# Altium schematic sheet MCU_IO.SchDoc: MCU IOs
size A3; Date: Not used; ApprovedBy: Not used; CheckedBy: Not used; Author: Not used; CompanyName: STMicroelectronics; DrawnBy: Not used; Engineer: Not used; Organization: Not used; Address1: Not used; Address2: Not used; Address3: Not used; Address4: Not used; DocumentNumber: 3; Revision: Not used; SheetNumber: 3; SheetTotal: 16
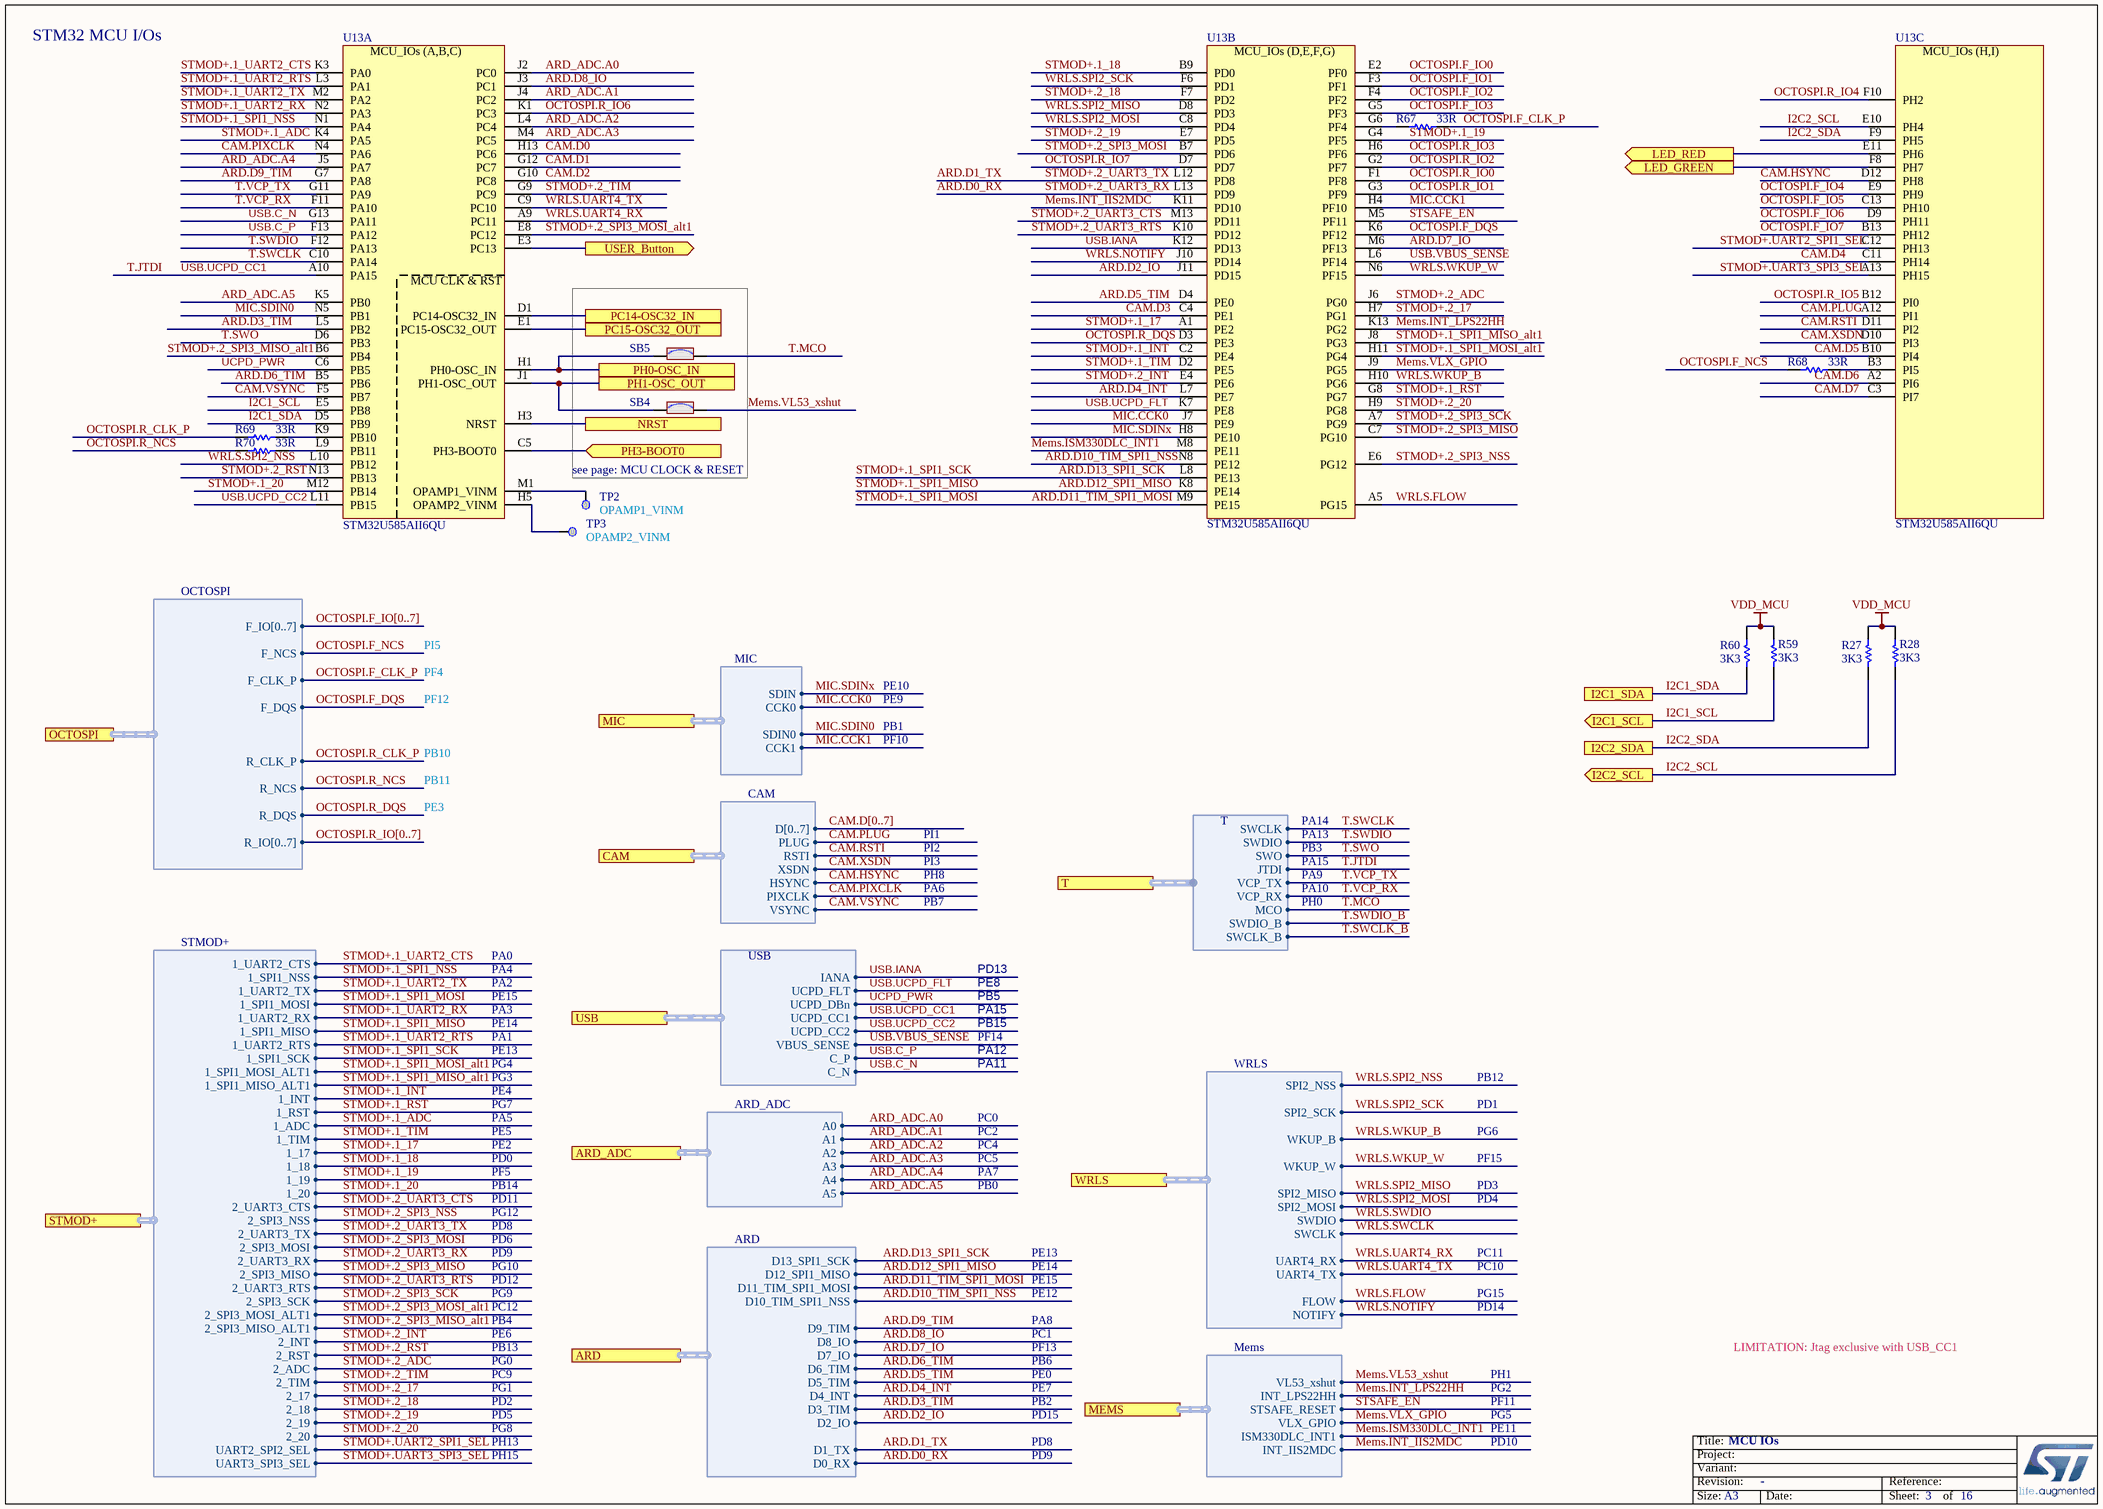
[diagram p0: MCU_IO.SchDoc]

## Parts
R27  value 3K3  [R0603]  (hidden comment: Resistor)
R28  value 3K3  [R0603]  (hidden comment: Resistor)
R59  value 3K3  [R0603]  (hidden comment: Resistor)
R60  value 3K3  [R0603]  (hidden comment: Resistor)
R67  value 33R  [R0402]  (hidden comment: Resistor)
R68  value 33R  [R0402]  (hidden comment: Resistor)
R69  value 33R  [R0402]  (hidden comment: Resistor)
R70  value 33R  [R0402]  (hidden comment: Resistor)
SB4  (no value)  [SOLDER-BRIDGE_R0603-0R]
SB5  (no value)  [SOLDER-BRIDGE_R0603-0R]
TP2  value OPAMP1_VINM  [TP_SMD_1MM]  (no BOM)
TP3  value OPAMP2_VINM  [TP_SMD_1MM]  (no BOM)
U13  STM32U585AII6QU  [ICC_UFBGA169_7X7_P050]  (parts A,B,C of 4)

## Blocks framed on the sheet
see page: MCU CLOCK & RESET: SB4 SB5

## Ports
ARD (harness ARD), ARD_ADC (harness ARD_ADC), CAM (harness CAM), I2C1_SCL (out), I2C1_SDA, I2C2_SCL (out), I2C2_SDA, LED_GREEN (out), LED_RED (out), MEMS (harness Mems), MIC (harness MIC), NRST, OCTOSPI (harness OCTOSPI), PC14-OSC32_IN, PC15-OSC32_OUT, PH0-OSC_IN, PH1-OSC_OUT, PH3-BOOT0 (in), STMOD+ (harness STMOD+), T (harness T), USB (harness USB), USER_Button (out), WRLS (harness WRLS)

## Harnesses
OCTOSPI: F_DQS, F_CLK_P, F_NCS, R_CLK_P, R_NCS, R_DQS, R_IO[0..7], F_IO[0..7]
STMOD+: 1_UART2_CTS, 1_SPI1_NSS, 1_UART2_TX, 1_SPI1_MOSI, 1_SPI1_MISO, 1_UART2_RTS, 1_ADC, 1_17, 1_18, 1_19, 1_20, 2_UART3_CTS, 2_SPI3_NSS, 2_UART3_TX, 2_SPI3_MOSI, 2_SPI3_MISO, 2_UART3_RTS, 2_UART3_RX, 1_UART2_RX, 1_SPI1_MOSI_ALT1, 2_SPI3_SCK, 2_SPI3_MOSI_ALT1, 1_SPI1_MISO_ALT1, 1_SPI1_SCK, 1_RST, 1_INT, 1_TIM, 2_SPI3_MISO_ALT1, 2_INT, 2_RST, 2_ADC, 2_TIM, 2_17, 2_18, 2_19, 2_20, UART2_SPI2_SEL, UART3_SPI3_SEL
ARD_ADC: A0, A1, A2, A3, A4, A5
ARD: D0_RX, D1_TX, D2_IO, D3_TIM, D4_INT, D5_TIM, D6_TIM, D7_IO, D8_IO, D9_TIM, D10_TIM_SPI1_NSS, D11_TIM_SPI1_MOSI, D12_SPI1_MISO, D13_SPI1_SCK
CAM: D[0..7], PLUG, XSDN, HSYNC, PIXCLK, VSYNC, RSTI
MIC: SDIN, CCK0, SDIN0, CCK1
WRLS: WKUP_B, WKUP_W, SPI2_NSS, SPI2_SCK, SPI2_MISO, SPI2_MOSI, SWDIO, SWCLK, UART4_RX, UART4_TX, FLOW, NOTIFY
USB: UCPD_FLT, UCPD_DBn, UCPD_CC2, VBUS_SENSE, C_P, C_N, UCPD_CC1, IANA
Mems: INT_LPS22HH, VLX_GPIO, ISM330DLC_INT1, INT_IIS2MDC, STSAFE_RESET, VL53_xshut
T: SWCLK, SWDIO, SWO, JTDI, VCP_RX, VCP_TX, MCO, SWDIO_B, SWCLK_B

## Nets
VDD_MCU: R27.1 R28.1 R59.1 R60.1
ARD.D0_RX: U13.L13(PD9) ; port STMOD+.2_UART3_RX, port ARD.D0_RX  [also labelled STMOD+.2_UART3_RX]
ARD.D1_TX: U13.L12(PD8) ; port STMOD+.2_UART3_TX, port ARD.D1_TX  [also labelled STMOD+.2_UART3_TX]
ARD.D2_IO: U13.J11(PD15) ; port ARD.D2_IO
ARD.D3_TIM: U13.L5(PB2) ; port ARD.D3_TIM
ARD.D4_INT: U13.L7(PE7) ; port ARD.D4_INT
ARD.D5_TIM: U13.D4(PE0) ; port ARD.D5_TIM
ARD.D6_TIM: U13.B5(PB6) ; port ARD.D6_TIM
ARD.D7_IO: U13.M6(PF13) ; port ARD.D7_IO
ARD.D8_IO: U13.J3(PC1) ; port ARD.D8_IO
ARD.D9_TIM: U13.G7(PA8) ; port ARD.D9_TIM
ARD.D10_TIM_SPI1_NSS: U13.N8(PE12) ; port ARD.D10_TIM_SPI1_NSS
ARD.D11_TIM_SPI1_MOSI: U13.M9(PE15) ; port STMOD+.1_SPI1_MOSI, port ARD.D11_TIM_SPI1_MOSI  [also labelled STMOD+.1_SPI1_MOSI]
ARD.D12_SPI1_MISO: U13.K8(PE14) ; port STMOD+.1_SPI1_MISO, port ARD.D12_SPI1_MISO  [also labelled STMOD+.1_SPI1_MISO]
ARD.D13_SPI1_SCK: U13.L8(PE13) ; port STMOD+.1_SPI1_SCK, port ARD.D13_SPI1_SCK  [also labelled STMOD+.1_SPI1_SCK]
ARD_ADC.A0: U13.J2(PC0) ; port ARD_ADC.A0
ARD_ADC.A1: U13.J4(PC2) ; port ARD_ADC.A1
ARD_ADC.A2: U13.L4(PC4) ; port ARD_ADC.A2
ARD_ADC.A3: U13.M4(PC5) ; port ARD_ADC.A3
ARD_ADC.A4: U13.J5(PA7) ; port ARD_ADC.A4
ARD_ADC.A5: U13.K5(PB0) ; port ARD_ADC.A5
CAM.D0: U13.H13(PC6)
CAM.D1: U13.G12(PC7)
CAM.D2: U13.G10(PC8)
CAM.D3: U13.C4(PE1)
CAM.D4: U13.C11(PH14)
CAM.D5: U13.B10(PI4)
CAM.D6: U13.A2(PI6)
CAM.D7: U13.C3(PI7)
CAM.HSYNC: U13.D12(PH8) ; port CAM.HSYNC
CAM.PIXCLK: U13.N4(PA6) ; port CAM.PIXCLK
CAM.PLUG: U13.A12(PI1) ; port CAM.PLUG
CAM.RSTI: U13.D11(PI2) ; port CAM.RSTI
CAM.VSYNC: U13.F5(PB7) ; port CAM.VSYNC
CAM.XSDN: U13.D10(PI3) ; port CAM.XSDN
I2C1_SCL: R59.2 U13.E5(PB8) ; port I2C1_SCL
I2C1_SDA: R60.2 U13.D5(PB9) ; port I2C1_SDA
I2C2_SCL: R28.2 U13.E10(PH4) ; port I2C2_SCL
I2C2_SDA: R27.2 U13.F9(PH5) ; port I2C2_SDA
LED_GREEN: U13.F8(PH7) ; port LED_GREEN
LED_RED: U13.E11(PH6) ; port LED_RED
Mems.INT_IIS2MDC: U13.K11(PD10) ; port MEMS.INT_IIS2MDC
Mems.INT_LPS22HH: U13.K13(PG2) ; port MEMS.INT_LPS22HH
Mems.ISM330DLC_INT1: U13.M8(PE11) ; port MEMS.ISM330DLC_INT1
Mems.VL53_xshut: SB4.2 ; port MEMS.VL53_xshut
Mems.VLX_GPIO: U13.J9(PG5) ; port MEMS.VLX_GPIO
MIC.CCK0: U13.J7(PE9) ; port MIC.CCK0
MIC.CCK1: U13.H4(PF10) ; port MIC.CCK1
MIC.SDIN0: U13.N5(PB1) ; port MIC.SDIN0
MIC.SDINx: U13.H8(PE10) ; port MIC.SDIN
NRST: U13.H3(NRST) ; port NRST
OCTOSPI.F_CLK_P: R67.2 ; port OCTOSPI.F_CLK_P
OCTOSPI.F_DQS: U13.K6(PF12) ; port OCTOSPI.F_DQS
OCTOSPI.F_IO0: U13.E2(PF0)
OCTOSPI.F_IO1: U13.F3(PF1)
OCTOSPI.F_IO2: U13.F4(PF2)
OCTOSPI.F_IO3: U13.G5(PF3)
OCTOSPI.F_IO4: U13.E9(PH9)
OCTOSPI.F_IO5: U13.C13(PH10)
OCTOSPI.F_IO6: U13.D9(PH11)
OCTOSPI.F_IO7: U13.B13(PH12)
OCTOSPI.F_NCS: R68.1 ; port OCTOSPI.F_NCS
OCTOSPI.R_CLK_P: R69.1 ; port OCTOSPI.R_CLK_P
OCTOSPI.R_DQS: U13.D3(PE3) ; port OCTOSPI.R_DQS
OCTOSPI.R_IO0: U13.F1(PF8)
OCTOSPI.R_IO1: U13.G3(PF9)
OCTOSPI.R_IO2: U13.G2(PF7)
OCTOSPI.R_IO3: U13.H6(PF6)
OCTOSPI.R_IO4: U13.F10(PH2)
OCTOSPI.R_IO5: U13.B12(PI0)
OCTOSPI.R_IO6: U13.K1(PC3)
OCTOSPI.R_IO7: U13.D7(PD7)
OCTOSPI.R_NCS: R70.1 ; port OCTOSPI.R_NCS
PC14-OSC32_IN: U13.D1(PC14-OSC32_IN) ; port PC14-OSC32_IN
PC15-OSC32_OUT: U13.E1(PC15-OSC32_OUT) ; port PC15-OSC32_OUT
PH0-OSC_IN: SB5.1 U13.H1(PH0-OSC_IN) ; port PH0-OSC_IN
PH1-OSC_OUT: SB4.1 U13.J1(PH1-OSC_OUT) ; port PH1-OSC_OUT
PH3-BOOT0: U13.C5(PH3-BOOT0) ; port PH3-BOOT0
STMOD+.1_17: U13.A1(PE2) ; port STMOD+.1_17
STMOD+.1_18: U13.B9(PD0) ; port STMOD+.1_18
STMOD+.1_19: U13.G4(PF5) ; port STMOD+.1_19
STMOD+.1_20: U13.M12(PB14) ; port STMOD+.1_20
STMOD+.1_ADC: U13.K4(PA5) ; port STMOD+.1_ADC
STMOD+.1_INT: U13.C2(PE4) ; port STMOD+.1_INT
STMOD+.1_RST: U13.G8(PG7) ; port STMOD+.1_RST
STMOD+.1_SPI1_MISO_alt1: U13.J8(PG3) ; port STMOD+.1_SPI1_MISO_ALT1
STMOD+.1_SPI1_MOSI_alt1: U13.H11(PG4) ; port STMOD+.1_SPI1_MOSI_ALT1
STMOD+.1_SPI1_NSS: U13.N1(PA4) ; port STMOD+.1_SPI1_NSS
STMOD+.1_TIM: U13.D2(PE5) ; port STMOD+.1_TIM
STMOD+.1_UART2_CTS: U13.K3(PA0) ; port STMOD+.1_UART2_CTS
STMOD+.1_UART2_RTS: U13.L3(PA1) ; port STMOD+.1_UART2_RTS
STMOD+.1_UART2_RX: U13.N2(PA3) ; port STMOD+.1_UART2_RX
STMOD+.1_UART2_TX: U13.M2(PA2) ; port STMOD+.1_UART2_TX
STMOD+.2_17: U13.H7(PG1) ; port STMOD+.2_17
STMOD+.2_18: U13.F7(PD2) ; port STMOD+.2_18
STMOD+.2_19: U13.E7(PD5) ; port STMOD+.2_19
STMOD+.2_20: U13.H9(PG8) ; port STMOD+.2_20
STMOD+.2_ADC: U13.J6(PG0) ; port STMOD+.2_ADC
STMOD+.2_INT: U13.E4(PE6) ; port STMOD+.2_INT
STMOD+.2_RST: U13.N13(PB13) ; port STMOD+.2_RST
STMOD+.2_SPI3_MISO: U13.C7(PG10) ; port STMOD+.2_SPI3_MISO
STMOD+.2_SPI3_MISO_alt1: U13.B6(PB4) ; port STMOD+.2_SPI3_MISO_ALT1
STMOD+.2_SPI3_MOSI: U13.B7(PD6) ; port STMOD+.2_SPI3_MOSI
STMOD+.2_SPI3_MOSI_alt1: U13.E8(PC12) ; port STMOD+.2_SPI3_MOSI_ALT1
STMOD+.2_SPI3_NSS: U13.E6(PG12) ; port STMOD+.2_SPI3_NSS
STMOD+.2_SPI3_SCK: U13.A7(PG9) ; port STMOD+.2_SPI3_SCK
STMOD+.2_TIM: U13.G9(PC9) ; port STMOD+.2_TIM
STMOD+.2_UART3_CTS: U13.M13(PD11) ; port STMOD+.2_UART3_CTS
STMOD+.2_UART3_RTS: U13.K10(PD12) ; port STMOD+.2_UART3_RTS
STMOD+.UART2_SPI1_SEL: U13.C12(PH13) ; port STMOD+.UART2_SPI2_SEL
STMOD+.UART3_SPI3_SEL: U13.A13(PH15) ; port STMOD+.UART3_SPI3_SEL
STSAFE_EN: U13.M5(PF11) ; port MEMS.STSAFE_RESET
T.JTDI: U13.A10(PA15) ; port USB.UCPD_CC1, port T.JTDI  [also labelled USB.UCPD_CC1]
T.MCO: SB5.2 ; port T.MCO
T.SWCLK: U13.C10(PA14) ; port T.SWCLK
T.SWDIO: U13.F12(PA13) ; port T.SWDIO
T.SWO: U13.D6(PB3) ; port T.SWO
T.VCP_RX: U13.F11(PA10) ; port T.VCP_RX
T.VCP_TX: U13.G11(PA9) ; port T.VCP_TX
UCPD_PWR: U13.C6(PB5) ; port USB.UCPD_DBn
USB.C_N: U13.G13(PA11) ; port USB.C_N
USB.C_P: U13.F13(PA12) ; port USB.C_P
USB.IANA: U13.K12(PD13) ; port USB.IANA
USB.UCPD_CC2: U13.L11(PB15) ; port USB.UCPD_CC2
USB.UCPD_FLT: U13.K7(PE8) ; port USB.UCPD_FLT
USB.VBUS_SENSE: U13.L6(PF14) ; port USB.VBUS_SENSE
USER_Button: U13.E3(PC13) ; port USER_Button
WRLS.FLOW: U13.A5(PG15) ; port WRLS.FLOW
WRLS.NOTIFY: U13.J10(PD14) ; port WRLS.NOTIFY
WRLS.SPI2_MISO: U13.D8(PD3) ; port WRLS.SPI2_MISO
WRLS.SPI2_MOSI: U13.C8(PD4) ; port WRLS.SPI2_MOSI
WRLS.SPI2_NSS: U13.L10(PB12) ; port WRLS.SPI2_NSS
WRLS.SPI2_SCK: U13.F6(PD1) ; port WRLS.SPI2_SCK
WRLS.UART4_RX: U13.A9(PC11) ; port WRLS.UART4_RX
WRLS.UART4_TX: U13.C9(PC10) ; port WRLS.UART4_TX
WRLS.WKUP_B: U13.H10(PG6) ; port WRLS.WKUP_B
WRLS.WKUP_W: U13.N6(PF15) ; port WRLS.WKUP_W
NetR67_1: R67.1 U13.G6(PF4)
NetR68_2: R68.2 U13.B3(PI5)
NetR69_2: R69.2 U13.K9(PB10)
NetR70_2: R70.2 U13.L9(PB11)
NetTP2_1: TP2.1 U13.M1(OPAMP1_VINM)
NetTP3_1: TP3.1 U13.H5(OPAMP2_VINM)

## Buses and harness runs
bus CAM.D[0..7]
bus OCTOSPI.F_IO[0..7]
bus OCTOSPI.R_IO[0..7]

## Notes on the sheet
- STM32 MCU I/Os
- PI5
- PF12
- PF4
- PE9
- PE10
- PB10
- PB11
- PB1
- PF10
- PE3
- PI1
- PI2
- PA14
- PA13
- PB3
- PI3
- PH8
- PA6
- PB7
- PA15
- PA10
- PA9
- PH0
- PA0
- PA4
- PA2
- PE8
- PD13
- PE14
- PA3
- PE15
- PA1
- PE13
- PF14
- PB15
- PB5
- PA12
- PG3
- PG4
- PE4
- PA5
- PG7
- PC0
- PA11
- PB12
- PD1
- PE5
- PE2
- PD0
- PF5
- PB14
- PC2
- PC5
- PA7
- PC4
- PB0
- PD3
- PF15
- PG6
- PD11
- PG12
- PD8
- PD9
- PD6
- PD4
- PC11
- PG10
- PD12
- PG9
- PC12
- PB4
- PA8
- PE12
- PC10
- PD14
- PG15
- PE6
- PG0
- PC9
- PB13
- PG1
- PE0
- PB6
- PE7
- PC1
- PF13
- PG2
- PH1
- LIMITATION: Jtag exclusive with USB_CC1
- PD2
- PG8
- PD5
- PH13
- PH15
- PB2
- PD15
- PE11
- PD10
- PG5
- PF11

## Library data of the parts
R27 R28 R59 R60 = MCD-00352: Resistor,3K3,0603,1%,1/10W; Manufacturer_Part_Number: RC0603FR-073K3L; Manufacturer: YAGEO; ECCN_US: EAR99; ECCN_EU: NEC; Provided_By: SUBCO
R67-R70 = MCD-00455: Resistor, 33R, 0402, +/-1%, 1/16W; Part_Preference: Recommended; Manufacturer: YAGEO; Manufacturer_Part_Number: RC0402FR-0733RL; Component_Country_Of_Origin: China; ShowFields: YES; ID: 2821
SB4 SB5 = MCD-00071: Solder Bridge ON; Part_Type: Mechanical; Provided_By: Subcon; Initial_Board_Reference: mb1274
TP2 TP3 = MCD-00074: Test Point 1mm; Part_Type: Mechanical; Initial_Board_Reference: MB1274
U13 = MCD-02055: STM32U585AII6Q MCU,Low Power BGA169 7x7, pitch0.5, with encryption, Q for Int SMPS.; Part_Type: IC; Manufacturer: STMICROELECTRONICS; ECCN_US: 5A002A4; Provided_By: SUBCO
